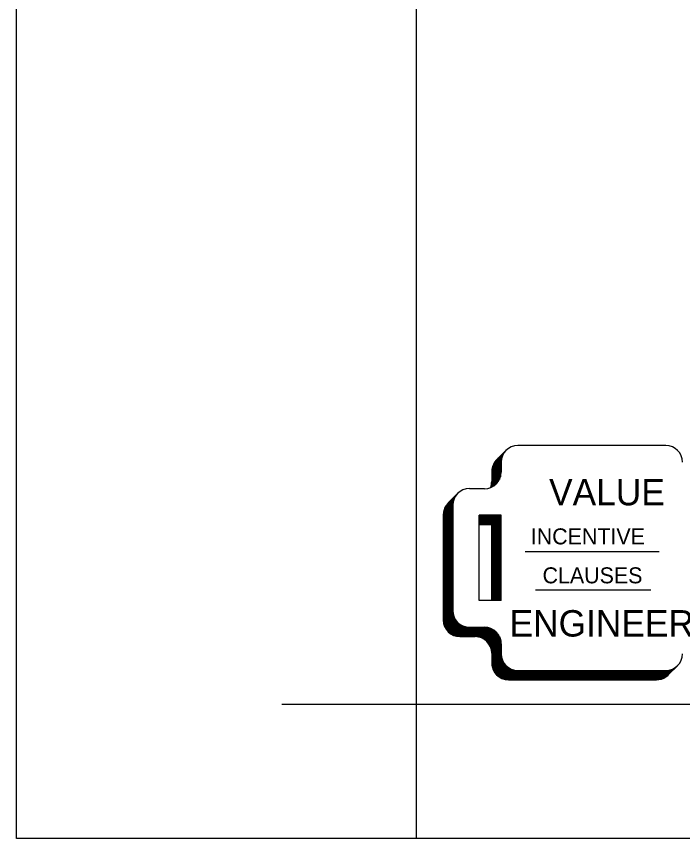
# Model space of a CAD drawing. Extents: x 22369.62 to 22373.29, y 22366.31 to 22369.14.
# Drawn here: x 22369.6213 to 22369.8295, y 22366.3082 to 22366.5653 of the extents above; entities that cross this region are included whole.
import ezdxf

# ---------------------------------------------------------------- set-up
doc = ezdxf.new("R2010")
doc.units = 0
for name, color, linetype in [('Level 1', 7, 'Continuous'), ('Level 10', 7, 'Continuous'), ('Level 2', 7, 'Continuous'), ('Level 7', 7, 'Continuous'), ('Level 9', 7, 'Continuous')]:
    doc.layers.add(name, color=color, linetype=linetype)

msp = doc.modelspace()

# ---------------------------------------------------------------- linework, layer by layer
at = {"layer": 'Level 1'}
msp.add_lwpolyline([(22369.6213, 22369.14218), (22373.2867, 22369.14218), (22373.2867, 22366.30818), (22369.6213, 22366.30818)], close=True, dxfattribs=at)
at = {"layer": 'Level 10'}
for p in [(22369.7043, 22366.35017), (22369.7463, 22366.30818)]:
    msp.add_line(p, (22369.7463, 22366.35017), dxfattribs=at)
at = {"layer": 'Level 2'}
for p, q in [((22369.77137, 22366.42662), (22369.77432, 22366.42957)), ((22369.77259, 22366.42784), (22369.77259, 22366.42135)), ((22369.7728, 22366.42588), (22369.7728, 22366.42805)), ((22369.77305, 22366.42748), (22369.77305, 22366.4283)), ((22369.77332, 22366.42815), (22369.77332, 22366.42857)), ((22369.77358, 22366.42862), (22369.77358, 22366.42883)), ((22369.7738, 22366.42896), (22369.7738, 22366.42905)), ((22369.77049, 22366.42543), (22369.77049, 22366.41848)), ((22369.77081, 22366.42595), (22369.77081, 22366.41872)), ((22369.77116, 22366.42639), (22369.77116, 22366.41902)), ((22369.77151, 22366.42676), (22369.77151, 22366.41937)), ((22369.77186, 22366.42711), (22369.77186, 22366.41983)), ((22369.77224, 22366.42749), (22369.77224, 22366.42046)), ((22369.76985, 22366.42294), (22369.76985, 22366.41812)), ((22369.77013, 22366.42462), (22369.77013, 22366.41827)), ((22369.75625, 22366.41313), (22369.7592, 22366.41608)), ((22369.75805, 22366.41433), (22369.75805, 22366.41494)), ((22369.75815, 22366.41457), (22369.75815, 22366.41504)), ((22369.75825, 22366.41477), (22369.75825, 22366.41513)), ((22369.75835, 22366.41497), (22369.75835, 22366.41524)), ((22369.75846, 22366.41513), (22369.75846, 22366.41534)), ((22369.75856, 22366.4153), (22369.75856, 22366.41545)), ((22369.75866, 22366.41545), (22369.75866, 22366.41555)), ((22369.75566, 22366.41243), (22369.75566, 22366.37355)), ((22369.75584, 22366.41266), (22369.75584, 22366.37331)), ((22369.75599, 22366.41284), (22369.75599, 22366.37313)), ((22369.75612, 22366.413), (22369.75612, 22366.37298)), ((22369.75627, 22366.41314), (22369.75627, 22366.37283)), ((22369.75645, 22366.41333), (22369.75645, 22366.37266)), ((22369.75657, 22366.41346), (22369.75657, 22366.37255)), ((22369.75671, 22366.41359), (22369.75671, 22366.37245)), ((22369.75687, 22366.41376), (22369.75687, 22366.37232)), ((22369.75705, 22366.41394), (22369.75705, 22366.3722)), ((22369.7572, 22366.41408), (22369.7572, 22366.3721)), ((22369.75733, 22366.41422), (22369.75733, 22366.37202)), ((22369.75747, 22366.41435), (22369.75747, 22366.37195)), ((22369.75756, 22366.41445), (22369.75756, 22366.37189)), ((22369.75768, 22366.41239), (22369.75768, 22366.41456)), ((22369.75779, 22366.41348), (22369.75779, 22366.41467)), ((22369.75794, 22366.41402), (22369.75794, 22366.41482)), ((22369.75487, 22366.41066), (22369.75487, 22366.37531)), ((22369.75503, 22366.4112), (22369.75503, 22366.37478)), ((22369.7552, 22366.4116), (22369.7552, 22366.37437)), ((22369.75533, 22366.41188), (22369.75533, 22366.37409)), ((22369.7555, 22366.41218), (22369.7555, 22366.3738)), ((22369.75473, 22366.40945), (22369.75473, 22366.37653)), ((22369.7728, 22366.40913), (22369.7659, 22366.40913)), ((22369.7728, 22366.409), (22369.7659, 22366.409)), ((22369.7728, 22366.40884), (22369.7659, 22366.40884)), ((22369.7728, 22366.40869), (22369.7659, 22366.40869)), ((22369.7728, 22366.40852), (22369.7659, 22366.40852)), ((22369.7728, 22366.40836), (22369.7659, 22366.40836)), ((22369.7728, 22366.40821), (22369.7659, 22366.40821)), ((22369.7728, 22366.40804), (22369.7659, 22366.40804)), ((22369.7728, 22366.40789), (22369.7659, 22366.40789)), ((22369.7728, 22366.40774), (22369.7659, 22366.40774)), ((22369.7728, 22366.40758), (22369.7659, 22366.40758)), ((22369.7728, 22366.40744), (22369.7659, 22366.40744)), ((22369.7728, 22366.40729), (22369.7659, 22366.40729)), ((22369.7728, 22366.40716), (22369.7659, 22366.40716)), ((22369.7728, 22366.40927), (22369.76985, 22366.40632)), ((22369.7728, 22366.40701), (22369.7659, 22366.40701)), ((22369.7728, 22366.40688), (22369.7659, 22366.40688)), ((22369.7728, 22366.40675), (22369.7659, 22366.40675)), ((22369.7728, 22366.40662), (22369.7659, 22366.40662)), ((22369.7728, 22366.40647), (22369.7659, 22366.40647)), ((22369.76985, 22366.40632), (22369.7659, 22366.40632)), ((22369.76985, 22366.3826), (22369.76985, 22366.40632)), ((22369.77, 22366.3826), (22369.77, 22366.40647)), ((22369.77011, 22366.3826), (22369.77011, 22366.40647)), ((22369.77024, 22366.3826), (22369.77024, 22366.40647)), ((22369.77034, 22366.3826), (22369.77034, 22366.40647)), ((22369.7705, 22366.3826), (22369.7705, 22366.40647)), ((22369.77063, 22366.3826), (22369.77063, 22366.40647)), ((22369.77078, 22366.3826), (22369.77078, 22366.40647)), ((22369.77088, 22366.3826), (22369.77088, 22366.40647)), ((22369.77105, 22366.3826), (22369.77105, 22366.40647)), ((22369.77119, 22366.3826), (22369.77119, 22366.40647)), ((22369.7713, 22366.3826), (22369.7713, 22366.40647)), ((22369.77144, 22366.3826), (22369.77144, 22366.40647)), ((22369.77157, 22366.3826), (22369.77157, 22366.40647)), ((22369.77173, 22366.3826), (22369.77173, 22366.40647)), ((22369.77185, 22366.3826), (22369.77185, 22366.40647)), ((22369.77198, 22366.3826), (22369.77198, 22366.40647)), ((22369.77213, 22366.3826), (22369.77213, 22366.40647)), ((22369.77229, 22366.3826), (22369.77229, 22366.40647)), ((22369.77245, 22366.3826), (22369.77245, 22366.40647)), ((22369.77255, 22366.3826), (22369.77255, 22366.40647)), ((22369.77269, 22366.3826), (22369.77269, 22366.40647)), ((22369.75775, 22366.37861), (22369.75775, 22366.3718)), ((22369.75791, 22366.37791), (22369.75791, 22366.37173)), ((22369.75807, 22366.37749), (22369.75807, 22366.37166)), ((22369.75823, 22366.37714), (22369.75823, 22366.37161)), ((22369.75841, 22366.3768), (22369.75841, 22366.37155)), ((22369.75855, 22366.37659), (22369.75855, 22366.37151)), ((22369.75869, 22366.37639), (22369.75869, 22366.37148)), ((22369.75886, 22366.37616), (22369.75886, 22366.37144)), ((22369.75901, 22366.376), (22369.75901, 22366.3714)), ((22369.75916, 22366.37583), (22369.75916, 22366.37138)), ((22369.75932, 22366.37568), (22369.75932, 22366.37135)), ((22369.75948, 22366.37554), (22369.75948, 22366.37134)), ((22369.75962, 22366.37541), (22369.75962, 22366.37133)), ((22369.7598, 22366.37528), (22369.7598, 22366.37132)), ((22369.75996, 22366.37516), (22369.75996, 22366.37132)), ((22369.76011, 22366.37507), (22369.76011, 22366.37132)), ((22369.76027, 22366.37498), (22369.76027, 22366.37132)), ((22369.76046, 22366.37487), (22369.76046, 22366.37132)), ((22369.76059, 22366.3748), (22369.76059, 22366.37132)), ((22369.76068, 22366.37476), (22369.76068, 22366.37132)), ((22369.76081, 22366.3747), (22369.76081, 22366.37132)), ((22369.76095, 22366.37464), (22369.76095, 22366.37132)), ((22369.76111, 22366.37458), (22369.76111, 22366.37132)), ((22369.76128, 22366.37452), (22369.76128, 22366.37132)), ((22369.76144, 22366.37448), (22369.76144, 22366.37132)), ((22369.76164, 22366.37441), (22369.76164, 22366.37132)), ((22369.76183, 22366.37437), (22369.76183, 22366.37132)), ((22369.76199, 22366.37434), (22369.76199, 22366.37132)), ((22369.7621, 22366.37433), (22369.7621, 22366.37132)), ((22369.76226, 22366.37431), (22369.76226, 22366.37132)), ((22369.76239, 22366.37429), (22369.76239, 22366.37132)), ((22369.76251, 22366.37428), (22369.76251, 22366.37132)), ((22369.76265, 22366.37427), (22369.76265, 22366.37132)), ((22369.76282, 22366.37427), (22369.76282, 22366.37132)), ((22369.76298, 22366.37427), (22369.76298, 22366.37132)), ((22369.76315, 22366.37427), (22369.76315, 22366.37132)), ((22369.76333, 22366.37427), (22369.76333, 22366.37132)), ((22369.76349, 22366.37427), (22369.76349, 22366.37132)), ((22369.7637, 22366.37427), (22369.7637, 22366.37132)), ((22369.76387, 22366.37427), (22369.76387, 22366.37132)), ((22369.76403, 22366.37427), (22369.76403, 22366.37132)), ((22369.76421, 22366.37427), (22369.76421, 22366.37132)), ((22369.7644, 22366.37427), (22369.7644, 22366.37132)), ((22369.76459, 22366.37427), (22369.76459, 22366.37132)), ((22369.76479, 22366.37427), (22369.76479, 22366.37132)), ((22369.76499, 22366.37427), (22369.76499, 22366.37132)), ((22369.76522, 22366.37427), (22369.76522, 22366.37129)), ((22369.76537, 22366.37427), (22369.76537, 22366.37127)), ((22369.76551, 22366.37427), (22369.76551, 22366.37125)), ((22369.76564, 22366.37427), (22369.76564, 22366.37123)), ((22369.76586, 22366.37427), (22369.76586, 22366.37118)), ((22369.76609, 22366.37427), (22369.76609, 22366.37111)), ((22369.76633, 22366.37427), (22369.76633, 22366.37104)), ((22369.76656, 22366.37427), (22369.76656, 22366.37096)), ((22369.76676, 22366.37427), (22369.76676, 22366.37087)), ((22369.76699, 22366.37427), (22369.76699, 22366.37077)), ((22369.76716, 22366.37427), (22369.76716, 22366.37068)), ((22369.76744, 22366.37427), (22369.76744, 22366.37051)), ((22369.76765, 22366.37427), (22369.76765, 22366.37036)), ((22369.76777, 22366.37427), (22369.76777, 22366.37028)), ((22369.76797, 22366.37427), (22369.76797, 22366.37012)), ((22369.76812, 22366.37424), (22369.76812, 22366.36999)), ((22369.76829, 22366.37422), (22369.76829, 22366.36983)), ((22369.76845, 22366.3742), (22369.76845, 22366.36968)), ((22369.76856, 22366.37418), (22369.76856, 22366.36955)), ((22369.76874, 22366.37414), (22369.76874, 22366.36933)), ((22369.76891, 22366.3741), (22369.76891, 22366.36909)), ((22369.7691, 22366.37405), (22369.7691, 22366.3688)), ((22369.76928, 22366.37399), (22369.76928, 22366.36849)), ((22369.76944, 22366.37394), (22369.76944, 22366.36815)), ((22369.7696, 22366.37386), (22369.7696, 22366.36771)), ((22369.76978, 22366.37379), (22369.76978, 22366.36698)), ((22369.76991, 22366.37373), (22369.76991, 22366.36224)), ((22369.75994, 22366.37132), (22369.76464, 22366.37132)), ((22369.77008, 22366.37363), (22369.77008, 22366.36151)), ((22369.77025, 22366.37354), (22369.77025, 22366.36105)), ((22369.7704, 22366.37345), (22369.7704, 22366.36071)), ((22369.77056, 22366.37334), (22369.77056, 22366.36041)), ((22369.77072, 22366.37323), (22369.77072, 22366.36016)), ((22369.77089, 22366.37309), (22369.77089, 22366.35991)), ((22369.77103, 22366.37298), (22369.77103, 22366.35974)), ((22369.77119, 22366.37283), (22369.77119, 22366.35956)), ((22369.77132, 22366.3727), (22369.77132, 22366.35941)), ((22369.77149, 22366.37252), (22369.77149, 22366.35925)), ((22369.77164, 22366.37233), (22369.77164, 22366.35911)), ((22369.77182, 22366.3721), (22369.77182, 22366.35896)), ((22369.77199, 22366.37185), (22369.77199, 22366.35883)), ((22369.77212, 22366.37163), (22369.77212, 22366.35874)), ((22369.77225, 22366.37139), (22369.77225, 22366.35865)), ((22369.77235, 22366.37118), (22369.77235, 22366.35859)), ((22369.77249, 22366.37084), (22369.77249, 22366.35851)), ((22369.7726, 22366.37049), (22369.7726, 22366.35845)), ((22369.7727, 22366.37009), (22369.7727, 22366.35839)), ((22369.76985, 22366.36611), (22369.76985, 22366.36304)), ((22369.77281, 22366.36565), (22369.77281, 22366.35834)), ((22369.77296, 22366.36472), (22369.77296, 22366.35828)), ((22369.77309, 22366.36427), (22369.77309, 22366.35822)), ((22369.77321, 22366.36397), (22369.77321, 22366.35818)), ((22369.77333, 22366.3637), (22369.77333, 22366.35812)), ((22369.77344, 22366.3635), (22369.77344, 22366.35809)), ((22369.77358, 22366.36325), (22369.77358, 22366.35805)), ((22369.77372, 22366.36304), (22369.77372, 22366.35801)), ((22369.77386, 22366.36283), (22369.77386, 22366.35797)), ((22369.77397, 22366.36271), (22369.77397, 22366.35795)), ((22369.77411, 22366.36253), (22369.77411, 22366.35791)), ((22369.7742, 22366.36244), (22369.7742, 22366.3579)), ((22369.77431, 22366.36232), (22369.77431, 22366.35788)), ((22369.77444, 22366.3622), (22369.77444, 22366.35787)), ((22369.77453, 22366.36211), (22369.77453, 22366.35786)), ((22369.77459, 22366.36206), (22369.77459, 22366.35785)), ((22369.77466, 22366.362), (22369.77466, 22366.35784)), ((22369.77478, 22366.3619), (22369.77478, 22366.35784)), ((22369.77493, 22366.36179), (22369.77493, 22366.35784)), ((22369.77509, 22366.36168), (22369.77509, 22366.35784)), ((22369.77524, 22366.36158), (22369.77524, 22366.35784)), ((22369.7754, 22366.36148), (22369.7754, 22366.35784)), ((22369.77556, 22366.36139), (22369.77556, 22366.35784)), ((22369.77572, 22366.36131), (22369.77572, 22366.35784)), ((22369.77584, 22366.36125), (22369.77584, 22366.35784)), ((22369.77599, 22366.36119), (22369.77599, 22366.35784)), ((22369.77615, 22366.36112), (22369.77615, 22366.35784)), ((22369.77632, 22366.36106), (22369.77632, 22366.35784)), ((22369.77649, 22366.36101), (22369.77649, 22366.35784)), ((22369.77666, 22366.36096), (22369.77666, 22366.35784)), ((22369.77685, 22366.3609), (22369.77685, 22366.35784)), ((22369.777, 22366.36087), (22369.777, 22366.35784)), ((22369.82504, 22366.35935), (22369.82799, 22366.3623)), ((22369.8253, 22366.35961), (22369.8253, 22366.36087)), ((22369.82543, 22366.35974), (22369.82543, 22366.3609)), ((22369.82553, 22366.35984), (22369.82553, 22366.36093)), ((22369.82564, 22366.35996), (22369.82564, 22366.36096)), ((22369.82577, 22366.36008), (22369.82577, 22366.36099)), ((22369.82585, 22366.36016), (22369.82585, 22366.36102)), ((22369.82596, 22366.36027), (22369.82596, 22366.36105)), ((22369.82605, 22366.36036), (22369.82605, 22366.36108)), ((22369.82615, 22366.36047), (22369.82615, 22366.36112)), ((22369.82622, 22366.36053), (22369.82622, 22366.36114)), ((22369.82634, 22366.36065), (22369.82634, 22366.3612)), ((22369.82644, 22366.36075), (22369.82644, 22366.36124)), ((22369.82654, 22366.36085), (22369.82654, 22366.36129)), ((22369.82665, 22366.36097), (22369.82665, 22366.36134)), ((22369.82675, 22366.36106), (22369.82675, 22366.36139)), ((22369.82684, 22366.36115), (22369.82684, 22366.36145)), ((22369.82694, 22366.36125), (22369.82694, 22366.3615)), ((22369.82704, 22366.36135), (22369.82704, 22366.36156)), ((22369.82714, 22366.36146), (22369.82714, 22366.36162)), ((22369.82724, 22366.36155), (22369.82724, 22366.36169)), ((22369.82733, 22366.36164), (22369.82733, 22366.36175)), ((22369.82742, 22366.36174), (22369.82742, 22366.36182)), ((22369.77719, 22366.36084), (22369.77719, 22366.35784)), ((22369.77735, 22366.36082), (22369.77735, 22366.35784)), ((22369.77752, 22366.3608), (22369.77752, 22366.35784)), ((22369.77772, 22366.36079), (22369.77772, 22366.35784)), ((22369.77788, 22366.36078), (22369.77788, 22366.35784)), ((22369.77788, 22366.36071), (22369.82135, 22366.36071)), ((22369.77788, 22366.36065), (22369.82135, 22366.36065)), ((22369.77788, 22366.3606), (22369.82135, 22366.3606)), ((22369.77788, 22366.36053), (22369.82135, 22366.36053)), ((22369.77788, 22366.36045), (22369.82135, 22366.36045)), ((22369.77788, 22366.36035), (22369.82135, 22366.36035)), ((22369.77788, 22366.36026), (22369.82135, 22366.36026)), ((22369.77788, 22366.36018), (22369.82135, 22366.36018)), ((22369.77788, 22366.36008), (22369.82135, 22366.36008)), ((22369.77788, 22366.35999), (22369.82135, 22366.35999)), ((22369.77788, 22366.35989), (22369.82135, 22366.35989)), ((22369.77788, 22366.3598), (22369.82135, 22366.3598)), ((22369.77788, 22366.35971), (22369.82135, 22366.35971)), ((22369.77788, 22366.35962), (22369.82135, 22366.35962)), ((22369.77788, 22366.35953), (22369.82135, 22366.35953)), ((22369.77788, 22366.35945), (22369.82135, 22366.35945)), ((22369.77788, 22366.35936), (22369.82135, 22366.35936)), ((22369.77788, 22366.35927), (22369.82135, 22366.35927)), ((22369.77788, 22366.35918), (22369.82135, 22366.35918)), ((22369.77788, 22366.35907), (22369.82135, 22366.35907)), ((22369.77788, 22366.35897), (22369.82135, 22366.35897)), ((22369.77788, 22366.35886), (22369.82135, 22366.35886)), ((22369.77788, 22366.35877), (22369.82135, 22366.35877)), ((22369.77788, 22366.35865), (22369.82135, 22366.35865)), ((22369.77788, 22366.35855), (22369.82135, 22366.35855)), ((22369.77788, 22366.35844), (22369.82135, 22366.35844)), ((22369.77788, 22366.35832), (22369.82135, 22366.35832)), ((22369.82135, 22366.35783), (22369.82135, 22366.36078)), ((22369.82147, 22366.35783), (22369.82147, 22366.36078)), ((22369.82155, 22366.35783), (22369.82155, 22366.36078)), ((22369.82163, 22366.35784), (22369.82163, 22366.36078)), ((22369.82177, 22366.35785), (22369.82177, 22366.36078)), ((22369.82187, 22366.35786), (22369.82187, 22366.36078)), ((22369.822, 22366.35787), (22369.822, 22366.36078)), ((22369.8221, 22366.35788), (22369.8221, 22366.36078)), ((22369.82222, 22366.3579), (22369.82222, 22366.36078)), ((22369.82231, 22366.35793), (22369.82231, 22366.36078)), ((22369.82244, 22366.35795), (22369.82244, 22366.36078)), ((22369.82255, 22366.35797), (22369.82255, 22366.36078)), ((22369.82266, 22366.358), (22369.82266, 22366.36078)), ((22369.82281, 22366.35804), (22369.82281, 22366.36078)), ((22369.82297, 22366.35809), (22369.82297, 22366.36078)), ((22369.82309, 22366.35813), (22369.82309, 22366.36078)), ((22369.82322, 22366.35818), (22369.82322, 22366.36078)), ((22369.82335, 22366.35823), (22369.82335, 22366.36078)), ((22369.82349, 22366.35829), (22369.82349, 22366.36078)), ((22369.8236, 22366.35834), (22369.8236, 22366.36078)), ((22369.82376, 22366.35843), (22369.82376, 22366.36078)), ((22369.82391, 22366.35851), (22369.82391, 22366.36078)), ((22369.82406, 22366.35859), (22369.82406, 22366.36078)), ((22369.82421, 22366.35869), (22369.82421, 22366.36078)), ((22369.82435, 22366.35878), (22369.82435, 22366.36078)), ((22369.82449, 22366.35888), (22369.82449, 22366.36078)), ((22369.82463, 22366.359), (22369.82463, 22366.36078)), ((22369.82479, 22366.35912), (22369.82479, 22366.3608)), ((22369.82494, 22366.35926), (22369.82494, 22366.36082)), ((22369.82506, 22366.35937), (22369.82506, 22366.36083)), ((22369.8252, 22366.35951), (22369.8252, 22366.36085)), ((22369.77506, 22366.35783), (22369.82135, 22366.35783)), ((22369.77788, 22366.3582), (22369.82135, 22366.3582)), ((22369.77788, 22366.35808), (22369.82135, 22366.35808)), ((22369.77788, 22366.35797), (22369.82135, 22366.35797))]:
    msp.add_line(p, q, dxfattribs=at)
for centre, start, end in [((22369.77506, 22366.42294), 111.4079, 180), ((22369.76464, 22366.41986), 338.5921, 0), ((22369.75993, 22366.40945), 111.4079, 180), ((22369.75993, 22366.37653), 180, 270), ((22369.76464, 22366.36611), 0, 90), ((22369.77506, 22366.36304), 180, 270), ((22369.82135, 22366.36304), 270, 338.5921)]:
    msp.add_arc(centre, 0.00521, start, end, dxfattribs=at)
at = {"layer": 'Level 7'}
for p, q in [((22369.8243, 22366.43109), (22369.77801, 22366.43109)), ((22369.7728, 22366.42588), (22369.7728, 22366.42281)), ((22369.76759, 22366.4176), (22369.76288, 22366.4176)), ((22369.75768, 22366.41239), (22369.75768, 22366.37948)), ((22369.7728, 22366.40927), (22369.7659, 22366.40927)), ((22369.7659, 22366.3826), (22369.7659, 22366.40927)), ((22369.7728, 22366.3826), (22369.7728, 22366.40927)), ((22369.78035, 22366.39795), (22369.82218, 22366.39795)), ((22369.7835, 22366.38595), (22369.81959, 22366.38595)), ((22369.7728, 22366.3826), (22369.7659, 22366.3826)), ((22369.76288, 22366.37427), (22369.76759, 22366.37427)), ((22369.7728, 22366.36906), (22369.7728, 22366.36599)), ((22369.77801, 22366.36078), (22369.8243, 22366.36078))]:
    msp.add_line(p, q, dxfattribs=at)
for centre, start, end in [((22369.778, 22366.42589), 90, 180), ((22369.82429, 22366.42589), 0, 90), ((22369.76759, 22366.42281), 270, 0), ((22369.76288, 22366.4124), 90, 180), ((22369.76288, 22366.37948), 180, 270), ((22369.76759, 22366.36906), 0, 90), ((22369.778, 22366.36599), 180, 270), ((22369.82429, 22366.36599), 270, 0)]:
    msp.add_arc(centre, 0.00521, start, end, dxfattribs=at)
at = {"layer": 'Level 9'}
for q in [(22369.7463, 22369.10017), (22373.0157, 22366.35017)]:
    msp.add_line((22369.7463, 22366.35017), q, dxfattribs=at)

# ---------------------------------------------------------------- texts
at = {"layer": 'Level 2'}
for s, height, p in [('VALUE', 0.008249, (22369.78779, 22366.41239)), ('INCENTIVE', 0.005, (22369.78208, 22366.40019)), ('CLAUSES', 0.005, (22369.78575, 22366.388)), ('ENGINEERING', 0.0082494, (22369.77544, 22366.37136))]:
    msp.add_text(s, height=height, dxfattribs=at).set_placement(p)

doc.saveas('drawing.dxf')
